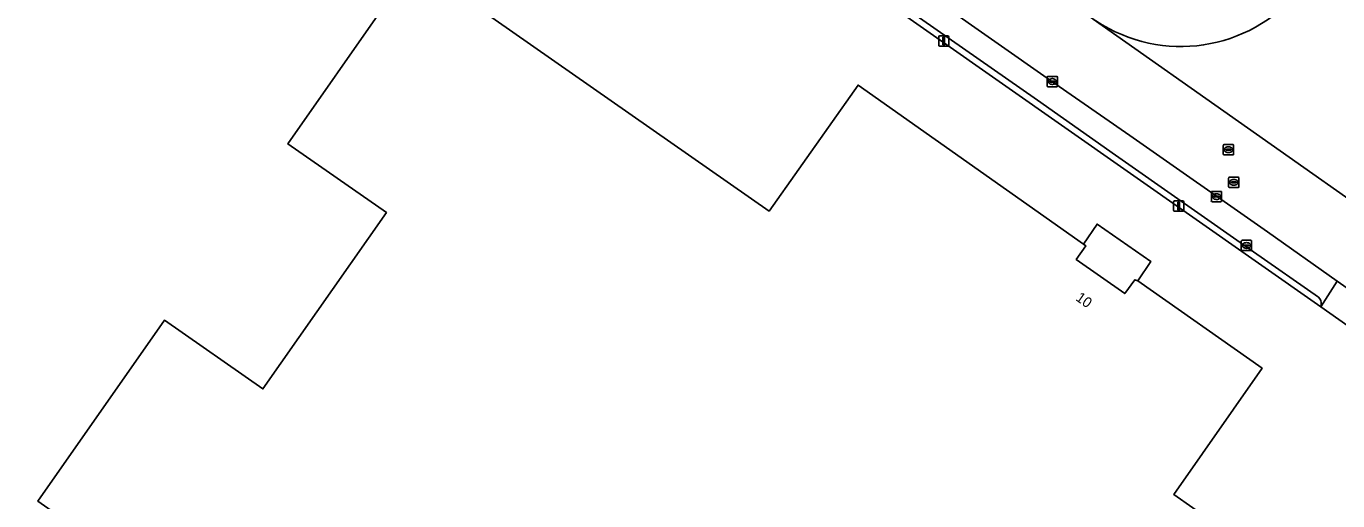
# Model space of a CAD drawing. Extents: x 155018 to 156648, y 383979 to 385733.
# Drawn here: x 155205.2 to 155332.5, y 384821.5 to 384867.6 of the extents above; entities that cross this region are included whole.
import ezdxf

# ---------------------------------------------------------------- set-up
doc = ezdxf.new("R2010")
doc.units = 0
for name, color, linetype in [('IMGEO_Brandkraan', 7, 'Continuous'), ('IMGEO_Erf', 7, 'Continuous'), ('IMGEO_Kolk', 7, 'Continuous'), ('IMGEO_Lichtmast', 7, 'Continuous'), ('IMGEO_Pand', 7, 'Continuous'), ('IMGEO_Pand_nummerreeks', 7, 'Continuous'), ('IMGEO_Pand_overbouw', 7, 'Continuous'), ('IMGEO_Parkeervlak_open', 7, 'Continuous'), ('IMGEO_Rijbaan_lokaal_gesloten', 7, 'Continuous'), ('IMGEO_Rijbaan_lokaal_open', 7, 'Continuous'), ('IMGEO_Rioolput', 7, 'Continuous'), ('IMGEO_Voetpad_open', 7, 'Continuous')]:
    doc.layers.add(name, color=color, linetype=linetype)

msp = doc.modelspace()

# ---------------------------------------------------------------- linework, layer by layer
at = {"layer": 'IMGEO_Brandkraan'}
for p, q in [((155323.18, 384845.9), (155323.18, 384846.75)), ((155323.25, 384846.83), (155324.11, 384846.83)), ((155323.48, 384846.37), (155323.88, 384846.37)), ((155323.67, 384846.61), (155323.69, 384846.61)), ((155324.18, 384846.75), (155324.18, 384845.9)), ((155324.11, 384845.83), (155323.25, 384845.83)), ((155323.44, 384846.32), (155323.44, 384846.33)), ((155323.88, 384846.28), (155323.48, 384846.28)), ((155323.69, 384846.05), (155323.67, 384846.05)), ((155323.92, 384846.33), (155323.92, 384846.32))]:
    msp.add_line(p, q, dxfattribs=at)
for points in [[(155323.18, 384845.9), (155323.18, 384846.75)], [(155323.25, 384846.83), (155324.11, 384846.83)], [(155324.18, 384846.75), (155324.18, 384845.9)], [(155324.11, 384845.83), (155323.25, 384845.83)]]:
    msp.add_lwpolyline(points, dxfattribs=at)
for centre, radius, start, end in [((155323.26, 384846.75), 0.0765, 91.552, 178.448), ((155323.26, 384846.75), 0.0765, 91.552, 178.448), ((155323.48, 384846.33), 0.0403, 85.8775, 175.7526), ((155323.88, 384846.33), 0.0386, 1.7309, 96.639), ((155324.1, 384846.75), 0.0765, 1.552, 88.448), ((155324.1, 384846.75), 0.0765, 1.552, 88.448), ((155323.26, 384845.9), 0.0765, 181.552, 268.448), ((155323.26, 384845.9), 0.0765, 181.552, 268.448), ((155323.48, 384846.32), 0.0366, 178.938, 274.7102), ((155323.88, 384846.33), 0.043, 264.8664, 352.4533), ((155324.1, 384845.9), 0.0765, 271.552, 358.448), ((155324.1, 384845.9), 0.0765, 271.552, 358.448)]:
    msp.add_arc(centre, radius, start, end, dxfattribs=at)
for centre, major_axis, ratio, start_param, end_param in [((155323.67, 384846.33), (-0.387, 0.002), 0.722429, 4.712389, 7.853982), ((155323.69, 384846.33), (-0.39, 0.002), 0.717154, 1.570796, 4.712389)]:
    msp.add_ellipse(centre, major_axis=major_axis, ratio=ratio, start_param=start_param, end_param=end_param, dxfattribs=at)
at = {"layer": 'IMGEO_Erf'}
msp.add_lwpolyline([(155335.26, 384837.31), (155330.9, 384840.37), (155281.19, 384875.23), (155281, 384875.36), (155276.21, 384878.76), (155276.08, 384878.86), (155237.97, 384905.51), (155237.77, 384905.65), (155231.32, 384910.2), (155230.96, 384910.46), (155227.04, 384913.16), (155223.51, 384907.87), (155222.62, 384906.56), (155222.49, 384906.53), (155220.95, 384907.55), (155220.91, 384907.73), (155221.82, 384909.03), (155221.99, 384909.07), (155221.44, 384909.46), (155224.68, 384914.48), (155224.48, 384914.55), (155216.48, 384920.23), (155216.59, 384920.39), (155102.88, 385000)], dxfattribs=at)
msp.add_lwpolyline([(155307.85, 384846.47), (155308.08, 384846.3), (155307.16, 384844.98), (155311.87, 384841.65), (155312.84, 384843), (155313.12, 384842.89), (155325.2, 384834.41), (155316.62, 384822.15), (155331.37, 384811.8), (155328.5, 384807.71), (155294.79, 384759.56), (155206.34, 384821.5), (155218.64, 384839.08), (155228.19, 384832.39), (155240.18, 384849.52), (155230.62, 384856.2), (155240.04, 384869.66), (155242.91, 384873.76), (155277.33, 384849.67), (155285.97, 384861.91)], close=True, dxfattribs=at)
at = {"layer": 'IMGEO_Kolk'}
for p, q in [((155304.33, 384861.82), (155304.33, 384862.67)), ((155304.41, 384862.75), (155305.26, 384862.75)), ((155305.26, 384861.75), (155304.41, 384861.75)), ((155304.59, 384862.24), (155304.59, 384862.25)), ((155304.63, 384862.29), (155305.03, 384862.29)), ((155305.03, 384862.2), (155304.63, 384862.2)), ((155304.82, 384862.53), (155304.84, 384862.53)), ((155304.84, 384861.97), (155304.82, 384861.97)), ((155305.07, 384862.25), (155305.07, 384862.24)), ((155305.33, 384862.67), (155305.33, 384861.82)), ((155320.27, 384850.65), (155320.27, 384851.51)), ((155320.34, 384851.58), (155321.19, 384851.58)), ((155321.27, 384851.51), (155321.27, 384850.65)), ((155321.19, 384850.58), (155320.34, 384850.58)), ((155320.52, 384851.07), (155320.52, 384851.09)), ((155320.96, 384851.04), (155320.56, 384851.04)), ((155320.57, 384851.12), (155320.96, 384851.12)), ((155320.75, 384851.36), (155320.78, 384851.36)), ((155320.78, 384850.8), (155320.75, 384850.8)), ((155321.01, 384851.09), (155321.01, 384851.07))]:
    msp.add_line(p, q, dxfattribs=at)
for points in [[(155304.33, 384861.82), (155304.33, 384862.67)], [(155304.41, 384862.75), (155305.26, 384862.75)], [(155305.26, 384861.75), (155304.41, 384861.75)], [(155305.33, 384862.67), (155305.33, 384861.82)], [(155320.27, 384850.65), (155320.27, 384851.51)], [(155320.34, 384851.58), (155321.19, 384851.58)], [(155321.27, 384851.51), (155321.27, 384850.65)], [(155321.19, 384850.58), (155320.34, 384850.58)]]:
    msp.add_lwpolyline(points, dxfattribs=at)
for centre, radius, start, end in [((155304.41, 384862.67), 0.0765, 91.552, 178.448), ((155304.41, 384862.67), 0.0765, 91.552, 178.448), ((155304.41, 384861.82), 0.0765, 181.552, 268.448), ((155304.41, 384861.82), 0.0765, 181.552, 268.448), ((155304.63, 384862.25), 0.0403, 85.8775, 175.7526), ((155304.63, 384862.24), 0.0366, 178.938, 274.7102), ((155305.04, 384862.25), 0.0386, 1.7309, 96.639), ((155305.03, 384862.25), 0.043, 264.8664, 352.4533), ((155305.26, 384862.67), 0.0765, 1.552, 88.448), ((155305.26, 384862.67), 0.0765, 1.552, 88.448), ((155305.26, 384861.82), 0.0765, 271.552, 358.448), ((155305.26, 384861.82), 0.0765, 271.552, 358.448), ((155320.34, 384851.51), 0.0765, 91.552, 178.448), ((155320.34, 384851.51), 0.0765, 91.552, 178.448), ((155321.19, 384851.51), 0.0765, 1.552, 88.448), ((155321.19, 384851.51), 0.0765, 1.552, 88.448), ((155320.34, 384850.66), 0.0765, 181.552, 268.448), ((155320.34, 384850.66), 0.0765, 181.552, 268.448), ((155320.56, 384851.08), 0.0403, 85.8775, 175.7526), ((155320.56, 384851.07), 0.0366, 178.938, 274.7102), ((155320.97, 384851.09), 0.0386, 1.7309, 96.639), ((155320.97, 384851.08), 0.043, 264.8664, 352.4533), ((155321.19, 384850.66), 0.0765, 271.552, 358.448), ((155321.19, 384850.66), 0.0765, 271.552, 358.448)]:
    msp.add_arc(centre, radius, start, end, dxfattribs=at)
for centre, major_axis, ratio, start_param, end_param in [((155304.82, 384862.25), (-0.387, 0.002), 0.722429, 4.712389, 7.853982), ((155304.84, 384862.25), (-0.39, 0.002), 0.717154, 1.570796, 4.712389), ((155320.75, 384851.08), (-0.387, 0.002), 0.722429, 4.712389, 7.853982), ((155320.78, 384851.08), (-0.39, 0.002), 0.717154, 1.570796, 4.712389)]:
    msp.add_ellipse(centre, major_axis=major_axis, ratio=ratio, start_param=start_param, end_param=end_param, dxfattribs=at)
at = {"layer": 'IMGEO_Lichtmast'}
for p, q in [((155293.8, 384865.79), (155293.8, 384866.59)), ((155293.8, 384866.59), (155293.8, 384865.79)), ((155293.9, 384866.69), (155294.68, 384866.69)), ((155294.68, 384866.69), (155293.9, 384866.69)), ((155294.68, 384865.69), (155293.9, 384865.69)), ((155293.9, 384865.69), (155294.68, 384865.69)), ((155294.78, 384866.59), (155294.78, 384865.79)), ((155294.78, 384865.79), (155294.78, 384866.59)), ((155316.6, 384849.76), (155316.6, 384850.55)), ((155316.6, 384850.55), (155316.6, 384849.76)), ((155316.7, 384850.65), (155317.49, 384850.65)), ((155317.49, 384850.65), (155316.7, 384850.65)), ((155317.59, 384850.55), (155317.59, 384849.76)), ((155317.59, 384849.76), (155317.59, 384850.55)), ((155317.49, 384849.66), (155316.7, 384849.66)), ((155316.7, 384849.66), (155317.49, 384849.66))]:
    msp.add_line(p, q, dxfattribs=at)
for points in [[(155294.21, 384866.57), (155294.37, 384866.57), (155294.37, 384865.82), (155294.21, 384865.82), (155294.21, 384866.57)], [(155317.02, 384850.53), (155317.17, 384850.53), (155317.17, 384849.78), (155317.02, 384849.78), (155317.02, 384850.53)]]:
    msp.add_lwpolyline(points, dxfattribs=at)
for centre, start, end in [((155293.9, 384866.59), 90, 180), ((155293.9, 384866.59), 90, 180), ((155293.9, 384865.79), 180, 270), ((155293.9, 384865.79), 180, 270), ((155294.68, 384866.59), 0, 90), ((155294.68, 384866.59), 360, 90), ((155294.68, 384865.79), 270, 0), ((155294.68, 384865.79), 270, 0), ((155316.7, 384850.55), 90, 180), ((155316.7, 384850.55), 90, 180), ((155317.49, 384850.55), 0, 90), ((155317.49, 384850.55), 360, 90), ((155316.7, 384849.76), 180, 270), ((155316.7, 384849.76), 180, 270), ((155317.49, 384849.76), 270, 0), ((155317.49, 384849.76), 270, 0)]:
    msp.add_arc(centre, 0.1, start, end, dxfattribs=at)
at = {"layer": 'IMGEO_Pand'}
msp.add_lwpolyline([(155240.04, 384869.66), (155230.62, 384856.2), (155240.18, 384849.52), (155228.19, 384832.39), (155218.64, 384839.08), (155206.34, 384821.5), (155294.79, 384759.56), (155328.5, 384807.71), (155331.37, 384811.8), (155316.62, 384822.15), (155325.2, 384834.41), (155313.12, 384842.89), (155312.84, 384843), (155311.87, 384841.65), (155307.16, 384844.98), (155308.08, 384846.3), (155307.85, 384846.47), (155285.97, 384861.91), (155277.33, 384849.67), (155242.91, 384873.76)], close=True, dxfattribs=at)
at = {"layer": 'IMGEO_Pand_overbouw'}
msp.add_lwpolyline([(155307.85, 384846.47), (155308.08, 384846.3), (155307.16, 384844.98), (155311.87, 384841.65), (155312.84, 384843), (155313.12, 384842.89), (155314.41, 384844.77), (155309.18, 384848.41)], close=True, dxfattribs=at)
at = {"layer": 'IMGEO_Parkeervlak_open'}
for points in [[(155330.94, 384840.6), (155330.9, 384840.37), (155332.49, 384842.86), (155325.71, 384847.64), (155312.35, 384857.01), (155304.66, 384862.36), (155282.71, 384877.75)], [(155282.21, 384875.28), (155303.38, 384860.45), (155310.97, 384855.09), (155324.36, 384845.72), (155330.67, 384841.31)]]:
    msp.add_lwpolyline(points, dxfattribs=at)
msp.add_arc((155330.17, 384840.71), 0.78, 351.9145, 50.1172, dxfattribs=at)
at = {"layer": 'IMGEO_Rijbaan_lokaal_gesloten'}
for points in [[(155388.02, 384812.73), (155353.81, 384836.72), (155339.39, 384846.83), (155338.76, 384847.19), (155308.81, 384868.31), (155308.75, 384868.35), (155307.83, 384868.99), (155250.1, 384909.36), (155247.68, 384911.07), (155227.05, 384925.51), (155224.17, 384927.53), (155216.5, 384932.9), (155215.36, 384933.68), (155201.75, 384943.2), (155198.63, 384938.97), (155196.79, 384940.31), (155199.78, 384944.58), (155188.75, 384952.29), (155186.94, 384953.58), (155177.81, 384959.95), (155169.49, 384965.81)], [(155200.81, 384935.12), (155218.31, 384922.86), (155226.48, 384917.15), (155233, 384912.58), (155239.47, 384908.04), (155277.86, 384881.14), (155282.71, 384877.75), (155304.66, 384862.36), (155312.35, 384857.01), (155325.71, 384847.64), (155332.49, 384842.86), (155336.83, 384839.82), (155356.02, 384826.37), (155356.56, 384826), (155363.16, 384821.38)], [(155309.68, 384867.75), (155308.81, 384868.31), (155338.76, 384847.19), (155339.39, 384846.83)]]:
    msp.add_lwpolyline(points, dxfattribs=at)
msp.add_arc((155317.31, 384880.52), 14.87, 239.1467, 323.0935, dxfattribs=at)
at = {"layer": 'IMGEO_Rijbaan_lokaal_open'}
msp.add_lwpolyline([(155332.49, 384842.86), (155330.9, 384840.37), (155335.26, 384837.31), (155336.83, 384839.82)], close=True, dxfattribs=at)
at = {"layer": 'IMGEO_Rioolput'}
for p, q in [((155321.43, 384855.2), (155321.43, 384856.05)), ((155321.51, 384856.13), (155322.36, 384856.13)), ((155321.69, 384855.62), (155321.69, 384855.63)), ((155321.73, 384855.67), (155322.13, 384855.67)), ((155322.13, 384855.58), (155321.73, 384855.58)), ((155321.92, 384855.91), (155321.94, 384855.91)), ((155321.94, 384855.35), (155321.92, 384855.35)), ((155322.17, 384855.63), (155322.17, 384855.62)), ((155322.43, 384856.05), (155322.43, 384855.2)), ((155322.36, 384855.13), (155321.51, 384855.13)), ((155321.95, 384852.03), (155321.95, 384852.88)), ((155322.03, 384852.96), (155322.88, 384852.96)), ((155322.44, 384852.74), (155322.46, 384852.74)), ((155322.95, 384852.88), (155322.95, 384852.03)), ((155322.88, 384851.96), (155322.03, 384851.96)), ((155322.21, 384852.45), (155322.21, 384852.46)), ((155322.25, 384852.5), (155322.65, 384852.5)), ((155322.65, 384852.41), (155322.25, 384852.41)), ((155322.46, 384852.18), (155322.44, 384852.18)), ((155322.69, 384852.46), (155322.69, 384852.45))]:
    msp.add_line(p, q, dxfattribs=at)
for points in [[(155321.43, 384855.2), (155321.43, 384856.05)], [(155321.51, 384856.13), (155322.36, 384856.13)], [(155322.43, 384856.05), (155322.43, 384855.2)], [(155322.36, 384855.13), (155321.51, 384855.13)], [(155321.95, 384852.03), (155321.95, 384852.88)], [(155322.03, 384852.96), (155322.88, 384852.96)], [(155322.95, 384852.88), (155322.95, 384852.03)], [(155322.88, 384851.96), (155322.03, 384851.96)]]:
    msp.add_lwpolyline(points, dxfattribs=at)
for centre, radius, start, end in [((155321.51, 384856.05), 0.0765, 91.552, 178.448), ((155321.51, 384856.05), 0.0765, 91.552, 178.448), ((155321.73, 384855.63), 0.0403, 85.8775, 175.7526), ((155321.73, 384855.62), 0.0366, 178.938, 274.7102), ((155322.14, 384855.63), 0.0386, 1.7309, 96.639), ((155322.13, 384855.63), 0.043, 264.8664, 352.4533), ((155322.36, 384856.05), 0.0765, 1.552, 88.448), ((155322.36, 384856.05), 0.0765, 1.552, 88.448), ((155321.51, 384855.2), 0.0765, 181.552, 268.448), ((155321.51, 384855.2), 0.0765, 181.552, 268.448), ((155322.36, 384855.2), 0.0765, 271.552, 358.448), ((155322.36, 384855.2), 0.0765, 271.552, 358.448), ((155322.03, 384852.88), 0.0765, 91.552, 178.448), ((155322.03, 384852.88), 0.0765, 91.552, 178.448), ((155322.88, 384852.88), 0.0765, 1.552, 88.448), ((155322.88, 384852.88), 0.0765, 1.552, 88.448), ((155322.03, 384852.03), 0.0765, 181.552, 268.448), ((155322.03, 384852.03), 0.0765, 181.552, 268.448), ((155322.25, 384852.46), 0.0403, 85.8775, 175.7526), ((155322.25, 384852.45), 0.0366, 178.938, 274.7102), ((155322.66, 384852.46), 0.0386, 1.7309, 96.639), ((155322.65, 384852.46), 0.043, 264.8664, 352.4533), ((155322.88, 384852.03), 0.0765, 271.552, 358.448), ((155322.88, 384852.03), 0.0765, 271.552, 358.448)]:
    msp.add_arc(centre, radius, start, end, dxfattribs=at)
for centre, major_axis, ratio, start_param, end_param in [((155321.92, 384855.63), (-0.387, 0.002), 0.722429, 4.712389, 7.853982), ((155321.94, 384855.63), (-0.39, 0.002), 0.717154, 1.570796, 4.712389), ((155322.44, 384852.46), (-0.387, 0.002), 0.722429, 4.712389, 7.853982), ((155322.46, 384852.46), (-0.39, 0.002), 0.717154, 1.570796, 4.712389)]:
    msp.add_ellipse(centre, major_axis=major_axis, ratio=ratio, start_param=start_param, end_param=end_param, dxfattribs=at)
at = {"layer": 'IMGEO_Voetpad_open'}
for points in [[(155281.45, 384875.36), (155281.19, 384875.23), (155330.9, 384840.37), (155330.94, 384840.6)], [(155330.67, 384841.31), (155324.36, 384845.72), (155310.97, 384855.09), (155303.38, 384860.45), (155282.21, 384875.28)]]:
    msp.add_lwpolyline(points, dxfattribs=at)
for centre, radius, start, end in [((155317.31, 384880.52), 14.87, 239.1467, 323.0935), ((155330.17, 384840.71), 0.78, 351.9145, 50.1172)]:
    msp.add_arc(centre, radius, start, end, dxfattribs=at)

# ---------------------------------------------------------------- texts
at = {"layer": 'IMGEO_Pand_nummerreeks'}
msp.add_text('10', height=1, rotation=324.7046, dxfattribs=at).set_placement((155307.02, 384841.06))

doc.saveas('drawing.dxf')
